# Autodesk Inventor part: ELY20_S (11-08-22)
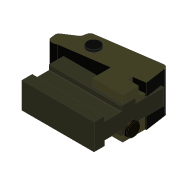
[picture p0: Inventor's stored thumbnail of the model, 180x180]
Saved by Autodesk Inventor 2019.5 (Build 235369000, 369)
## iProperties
Created: 2022-08
Part Number: ELY20_S (11-08-22)
Material: St37-2 / S235
Document SubType Name: Modeling
Designer: schoth
Density: 7.86 g/cm^3
Appearance: Steel
RuleStatus: InUse
Author: schoth
Mass(KG): 0.0
Area(mm): 0.0
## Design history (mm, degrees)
derived "ELY20.iam"
body "Solid1"
node "FB175-005.ipt:1"
node "ELY20-88.iam:1::FB179-030.ipt:1"
node "ELY20-88.iam:1::CS235-006.ipt:1"
node "ELY20-99.iam:1::FB176-011.ipt:1"
node "ELY20-99.iam:1::FB177-104.ipt:1"
node "ELY20.iam_Bodies"
